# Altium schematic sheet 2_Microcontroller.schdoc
size 309 x 223 mm; Symbol: Sheet-Symbol_A4; Device: Sheet-Symbol_A4; @Project Name: Digital_Watch_V01; @Page Count: 3; @Update Date: 2025-01-19; @Create Date: 2024-12-19; @Schematic Name: D-Watch_Sch_v1.4; @Page No: 2; @Page Name: Microcontroller; Company: EasyEDA.com; Reviewed: EasyEDA; Version: V0.1; Page Size: A4; Part Number: JLCPCB-002; Drawn: EasyEDA; @Board Name: D-Watch_Board_v1.4; @Create Time: 19:17:03; @Update Time: 13:36:54
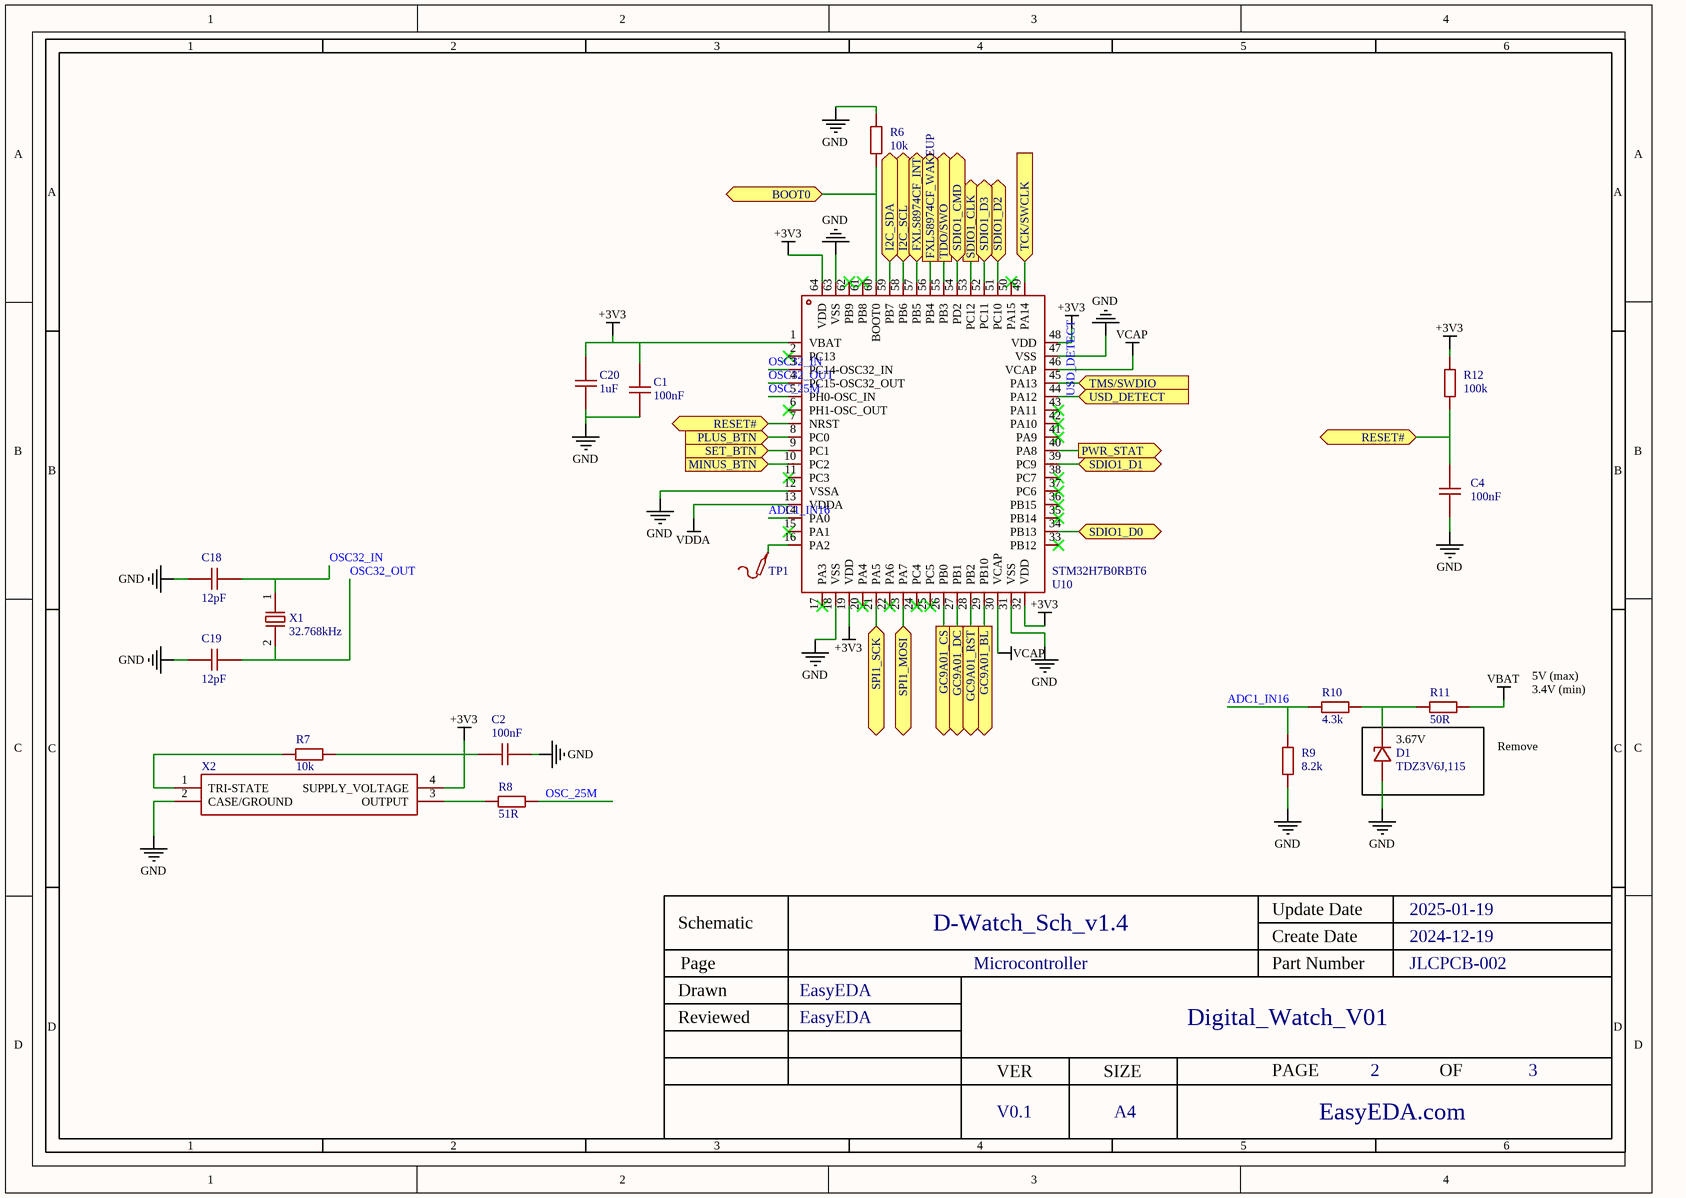
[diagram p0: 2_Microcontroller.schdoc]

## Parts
C1  100nF  [C0603]  (value not drawn)
C2  100nF  [C0603]  (value not drawn)
C4  100nF  [C0603]  (value not drawn)
C18  12pF  [C0603]  (value not drawn)
C19  12pF  [C0603]  (value not drawn)
C20  1uF  [C0603]  (value not drawn)
D1  TDZ3V6J,115  [SOD-323_L1.7-W1.3-LS2.5-RD-1]  (value not drawn)
R6  10k  [R0603]  (value not drawn)
R7  10k  [R0603]  (value not drawn)
R8  51R  [R0603]  (value not drawn)
R9  8.2k  [R0603]  (value not drawn)
R10  4.3k  [R0603]  (value not drawn)
R11  50R  [R0603]  (value not drawn)
R12  100k  [R0603]  (value not drawn)
TP1  Test-Point  [Test-Point-0.5mm]  (value not drawn)
U10  STM32H7B0RBT6  [LQFP-64_L10.0-W10.0-P0.50-LS12.0-BL]  (value not drawn)
X1  32.768kHz  [CRYSTAL-SMD_L3.2-W1.5-1]  (value not drawn)
X2  EC5625ETTTS-25.000M_TR_  [EC5625ETTTS25000MTR]  (value not drawn)

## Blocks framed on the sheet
3.67V: D1

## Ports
BOOT0 (bidir), FXLS8974CF_INT (bidir), FXLS8974CF_WAKEUP (out), GC9A01_BL (out), GC9A01_CS (out), GC9A01_DC (out), GC9A01_RST (out), I2C_SCL (bidir), I2C_SDA (bidir), MINUS_BTN (in), PLUS_BTN (in), PWR_STAT (out), RESET# (bidir), SDIO1_CLK (out), SDIO1_CMD (bidir), SDIO1_D0 (bidir), SDIO1_D1 (bidir), SDIO1_D2 (bidir), SDIO1_D3 (bidir), SET_BTN (in), SPI1_MOSI (bidir), SPI1_SCK (bidir), TCK/SWCLK (in), TDO/SWO (out), TMS/SWDIO (in), USD_DETECT (in)

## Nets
+3V3: C1.1 C2.1 C20.2 R7.2 R12.1 U10.1(VBAT) U10.19(VDD) U10.32(VDD) U10.48(VDD) U10.64(VDD) X2.4(SUPPLY_VOLTAGE)
GND: C1.2 C2.2 C4.2 C18.2 C19.2 C20.1 D1.2(A) R6.1 R9.2 U10.12(VSSA) U10.18(VSS) U10.31(VSS) U10.47(VSS) U10.63(VSS) X2.2(CASE/GROUND)
VBAT: R11.2
VCAP: U10.30(VCAP) U10.46(VCAP)
VDDA: U10.13(VDDA)
ADC1_IN16: R9.1 R10.1 U10.14(PA0)
BOOT0: R6.2 U10.60(BOOT0) ; port BOOT0
FXLS8974CF_INT: U10.57(PB5) ; port FXLS8974CF_INT
FXLS8974CF_WAKEUP: U10.56(PB4) ; port FXLS8974CF_WAKEUP
GC9A01_BL: U10.29(PB10) ; port GC9A01_BL
GC9A01_CS: U10.26(PB0) ; port GC9A01_CS
GC9A01_DC: U10.27(PB1) ; port GC9A01_DC
GC9A01_RST: U10.28(PB2) ; port GC9A01_RST
I2C_SCL: U10.58(PB6) ; port I2C_SCL
I2C_SDA: U10.59(PB7) ; port I2C_SDA
MINUS_BTN: U10.10(PC2) ; port MINUS_BTN
OSC32_IN: C18.1 U10.3(PC14-OSC32_IN) X1.1
OSC32_OUT: C19.1 U10.4(PC15-OSC32_OUT) X1.2
OSC_25M: R8.2 U10.5(PH0-OSC_IN)
PLUS_BTN: U10.8(PC0) ; port PLUS_BTN
PWR_STAT: U10.40(PA8) ; port PWR_STAT
RESET#: C4.1 R12.2 U10.7(NRST) ; port RESET#
SDIO1_CLK: U10.53(PC12) ; port SDIO1_CLK
SDIO1_CMD: U10.54(PD2) ; port SDIO1_CMD
SDIO1_D0: U10.34(PB13) ; port SDIO1_D0
SDIO1_D1: U10.39(PC9) ; port SDIO1_D1
SDIO1_D2: U10.51(PC10) ; port SDIO1_D2
SDIO1_D3: U10.52(PC11) ; port SDIO1_D3
SET_BTN: U10.9(PC1) ; port SET_BTN
SPI1_MOSI: U10.23(PA7) ; port SPI1_MOSI
SPI1_SCK: U10.21(PA5) ; port SPI1_SCK
TCK/SWCLK: U10.49(PA14) ; port TCK/SWCLK
TDO/SWO: U10.55(PB3) ; port TDO/SWO
TMS/SWDIO: U10.45(PA13) ; port TMS/SWDIO
USD_DETECT: U10.44(PA12) ; port USD_DETECT
NetD1_1: D1.1(C) R10.2 R11.1
NetR7_1: R7.1 X2.1(TRI-STATE)
NetR8_1: R8.1 X2.3(OUTPUT)
NetTP1_1: TP1.1 U10.16(PA2)

Not connected (* = marked no-connect by the designer): U10 2(PC13)* 6(PH1-OSC_OUT)* 11(PC3)* 15(PA1)* 17(PA3)* 20(PA4)* 22(PA6)* 24(PC4)* 25(PC5)* 33(PB12)* 35(PB14)* 36(PB15)* 37(PC6)* 38(PC7)* 41(PA9)* 42(PA10)* 43(PA11)* 50(PA15)* 61(PB8)* 62(PB9)*

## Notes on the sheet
- 5V (max)
  3.4V (min)
- (near R11) Remove

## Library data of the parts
C1 C2 C4 = GCJ188R71C104KA01D: Capacitance: Tolerance:±10% Tolerance:±10% Voltage Rated: Temperature Coefficient:; Manufacturer: muRata(村田); Add into BOM: yes; Tolerance: ±10%
C18 C19 = CAP_0603: Symbol: CAP; Convert to PCB: yes
C20 = AC0603KRX7R6BB105: Capacitance: Tolerance:±10% Tolerance:±10% Voltage Rated: Temperature Coefficient:; Manufacturer: YAGEO(国巨); Add into BOM: yes; Tolerance: ±10%
D1 = TDZ3V6J,115: Zener Voltage (Nom):3.6V Reverse Leakage Current (Ir):5uA@1V Power Dissipation:500mW Zener Impedance (Zzt):90Ω Tolerance:±2% Tolerance:±2%; Manufacturer: Nexperia(安世); Add into BOM: yes; Zener Voltage (Nom): 3.6V; Reverse Leakage Current (Ir): 5uA@1V; Power Dissipation: 500mW; Zener Impedance (Zzt): 90Ω; Tolerance: ±2%
R6-R12 = Res_0603: Symbol: Res; Convert to PCB: yes
TP1 = Test-Point: Test Point 测试点; Add into BOM: yes
U10 = STM32H7B0RBT6: CPU Core:- Program Storage Size:128KB GPIO Ports Number:49 Operating Voltage Range:1.62V~3.6V Operating Voltage Range:1.62V~3.6V CPU Maximum Speed:280MHz Operating Temperature Range:-40℃~+85℃ Operating Temperature Range:-40℃~+85℃ ADC (Bit):16bit DAC (Bit); Manufacturer: ST(意法半导体); Add into BOM: yes; Program Storage Size: 128KB; GPIO Ports Number: 49; CPU Maximum Speed: 280MHz; ADC (Bit): 16bit; DAC (Bit): 12bit
X1 = NX3215SA-32.768K-STD-MUA-9: Crystal Type:- Frequency: Normal temperature Frequency Tolerance:±20ppm Normal temperature Frequency Tolerance:±20ppm External load capacitor: Equivalent Series Resistance (ESR):70kΩ Operating Temperature: Operating Temperature:; Manufacturer: NDK; Add into BOM: yes; Normal temperature Frequency Tolerance: ±20ppm; Equivalent Series Resistance (ESR): 70kΩ
X2 = EC5625ETTTS-25.000M_TR_: Add into BOM: yes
